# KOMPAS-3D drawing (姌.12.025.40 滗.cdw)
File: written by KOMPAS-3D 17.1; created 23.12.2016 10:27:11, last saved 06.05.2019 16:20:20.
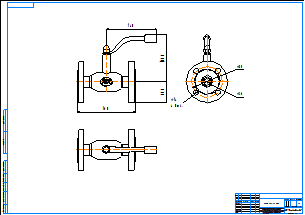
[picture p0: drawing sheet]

Sheet 1: A1, landscape

Title block, sheet 1: name: КШ.12.025.40 фф; material: Внимание! Данный продукт является объектом авторского права ООО «Торговый Дом АДЛ». / Запрещается изменение, копирование, распространение / (в том числе путем копирования на другие сайты и ресурсы в Интернете) / или любое иное использование информации и объектов без предварительного / согласия правообладателя (ООО «Торговый Дом АДЛ»).; sheets: 1; organisation: ООО "Торговый дом АДЛ"; sheet format: A1; stored path: C:\Users\tra\Desktop\2д чертежи\Шаровые краны БИВАЛ\КШ_Бивал_серия_11_12\KOMPAS_2D\КШ.12.025.40 фф.cdw

Views: Спереди 4, Проекционный вид 5, Проекционный вид 6
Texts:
  Klimkovich
  ADL
Dimensions and other numbers on the sheet: 160; 140; 130,2; 57,5; 85; 26; 14; 4 Отв.; 1:1; 1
